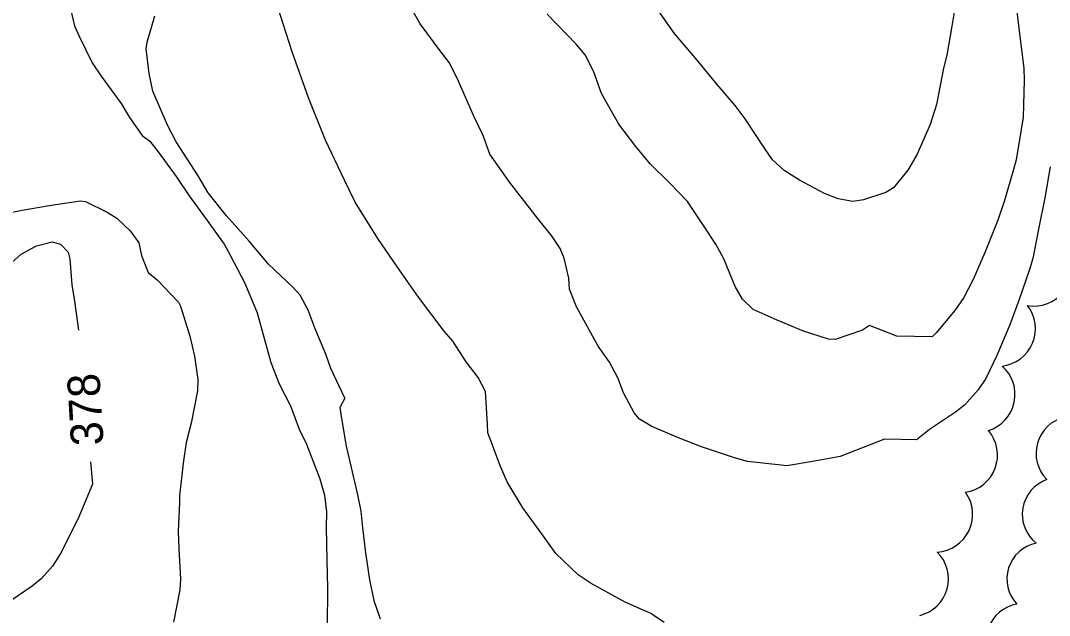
# Model space of a CAD drawing. Extents: x 287698 to 290158, y 5234163 to 5237182.
# Drawn here: x 288457.3 to 288552.3, y 5235862.5 to 5235917.4 of the extents above; entities that cross this region are included whole.
import ezdxf

# ---------------------------------------------------------------- set-up
doc = ezdxf.new("R2010")
doc.units = 0
for name, color, linetype in [('Niveau 1', 7, 'Continuous'), ('Niveau 2', 7, 'Continuous'), ('Niveau 44', 7, 'Continuous')]:
    doc.layers.add(name, color=color, linetype=linetype)

msp = doc.modelspace()

# ---------------------------------------------------------------- linework, layer by layer
at = {"layer": 'Niveau 1'}
for points in [[(288515.63, 5235862.61), (288514.75, 5235862.96), (288513.16, 5235863.68), (288510.03, 5235865.42), (288508.81, 5235866.19), (288506.76, 5235868.18), (288505.77, 5235869.56), (288503.71, 5235872.38), (288502.26, 5235874.79), (288501.66, 5235876.2), (288500.47, 5235879.32), (288500.44, 5235880.12), (288500.26, 5235883.13), (288499.58, 5235884.41), (288498.47, 5235885.86), (288497.23, 5235887.78), (288496.45, 5235888.7), (288494.08, 5235891.82), (288492.12, 5235894.61), (288490.31, 5235897.24), (288488.22, 5235900.59), (288487.25, 5235902.62), (288485.47, 5235906.33), (288483.91, 5235910.24), (288482.41, 5235914.47), (288481.02, 5235918.77)], [(288515.63, 5235862.61), (288516.77, 5235861.83)]]:
    msp.add_lwpolyline(points, dxfattribs=at)
at = {"layer": 'Niveau 2'}
for points in [[(288545.77, 5235939.08), (288547.74, 5235931.7), (288547.66, 5235931.66), (288548.19, 5235928.78), (288548.66, 5235927.21), (288549.54, 5235924.97), (288549.3, 5235922.31), (288549.15, 5235919.63), (288549.23, 5235918.97), (288549.61, 5235915.9), (288549.97, 5235912.96), (288550.01, 5235911.86), (288549.9, 5235908.44), (288549.72, 5235907.32), (288549.26, 5235904.52), (288549.01, 5235903.61), (288548.2, 5235900.76), (288547.56, 5235898.93), (288546.42, 5235896.01), (288545.31, 5235893.46), (288544.42, 5235891.81), (288543.59, 5235890.61), (288541.89, 5235888.53), (288541.5, 5235888.17)], [(288461.61, 5235919.93), (288462.29, 5235916.89), (288462.69, 5235915.99), (288463.93, 5235913.47), (288464.77, 5235912.23), (288466.62, 5235909.71), (288467.37, 5235908.41), (288468.56, 5235906.77), (288469.26, 5235906.23), (288470.02, 5235905.25), (288471.7, 5235902.96), (288472.88, 5235901.2), (288474.56, 5235898.9), (288476.13, 5235896.72), (288476.67, 5235895.7), (288478.02, 5235893.13), (288479.16, 5235890.4), (288479.59, 5235888.81), (288480.45, 5235885.8), (288481.2, 5235883.83), (288482.26, 5235881.79), (288483.05, 5235879.64), (288483.74, 5235878.27), (288484.95, 5235875.06), (288485.39, 5235873.57), (288485.59, 5235872.01), (288485.55, 5235870.56), (288485.61, 5235867.52), (288485.66, 5235864.97), (288485.64, 5235861.46)], [(288543.78, 5235919.66), (288543.32, 5235916.86), (288542.87, 5235914.16), (288542.57, 5235912.97), (288541.91, 5235909.62), (288541.32, 5235907.76), (288540.09, 5235904.97), (288539.27, 5235903.54), (288537.93, 5235901.91), (288537.22, 5235901.49), (288535.17, 5235900.81), (288534.18, 5235900.67), (288532.84, 5235900.91), (288531.56, 5235901.39), (288529.27, 5235902.63), (288527.84, 5235903.52), (288526.78, 5235904.51), (288526.04, 5235905.6), (288524.25, 5235908.29), (288523.33, 5235909.52), (288521.67, 5235911.47), (288519.8, 5235913.71), (288517.71, 5235916.18), (288517.04, 5235917.13), (288515.14, 5235919.88)], [(288540.09, 5235878.68), (288537.12, 5235878.73), (288533.01, 5235877.14), (288530.65, 5235876.7), (288528.08, 5235876.28), (288527.58, 5235876.33), (288524.45, 5235876.67), (288523.25, 5235877), (288520.21, 5235878.03), (288518.07, 5235878.84), (288515.63, 5235879.9), (288514.47, 5235880.57), (288513.98, 5235881.15), (288513.01, 5235882.99), (288512.47, 5235884.39), (288511.72, 5235885.84), (288510.66, 5235887.31), (288508.67, 5235890.94), (288508.03, 5235892.58), (288507.97, 5235893.6), (288507.54, 5235895.44), (288507.17, 5235896.33), (288506.37, 5235897.52), (288505.07, 5235899.11), (288502.52, 5235902.42), (288500.67, 5235905.04), (288500.03, 5235906.75), (288499.18, 5235908.53), (288497.65, 5235912.04), (288496.9, 5235913.5), (288496.06, 5235914.58), (288494.23, 5235917.07), (288493.47, 5235918.43)], [(288487.27, 5235882.52), (288485.99, 5235885.26), (288485.53, 5235886.57), (288484.53, 5235888.9), (288483.89, 5235890.64), (288483.14, 5235892.01), (288482.51, 5235892.74), (288480.22, 5235894.89), (288478.45, 5235897), (288476.33, 5235899.33), (288474.65, 5235901.47), (288473.74, 5235903.02), (288471.7, 5235906.16), (288470.89, 5235907.71), (288469.55, 5235910.85), (288469.19, 5235912.47), (288468.91, 5235914.76), (288469.03, 5235915.38), (288469.71, 5235917.81)], [(288541.5, 5235888.17), (288538.26, 5235888.23), (288535.71, 5235889.21), (288535.08, 5235888.78), (288532.56, 5235887.93), (288531.93, 5235887.96), (288529.64, 5235888.71), (288527.19, 5235889.7), (288524.98, 5235890.71), (288524, 5235891.65), (288523.32, 5235892.83), (288522.27, 5235895.37), (288521.52, 5235896.74), (288520.33, 5235898.53), (288518.93, 5235900.65), (288517.28, 5235902.35), (288515.48, 5235904.14), (288514.13, 5235905.75), (288512.56, 5235907.8), (288510.97, 5235910.63), (288510.22, 5235912.69), (288509.48, 5235914.19), (288508.64, 5235915.2), (288505.96, 5235917.96)], [(288552.4, 5235903.87), (288551.9, 5235900.99), (288551.34, 5235898.12), (288550.8, 5235895.39), (288550.5, 5235894.39), (288549.56, 5235891.63), (288548.67, 5235889.29), (288547.49, 5235886.46), (288546.46, 5235884.33), (288545.77, 5235883.29), (288544.51, 5235881.88), (288543.68, 5235881.23), (288541.26, 5235879.61), (288540.19, 5235878.76), (288540.09, 5235878.68)], [(288456.24, 5235899.61), (288457.46, 5235899.85), (288459.98, 5235900.28), (288462.87, 5235900.71), (288463.31, 5235900.66), (288465.33, 5235899.68), (288466.2, 5235899.12), (288467.46, 5235897.97), (288468.25, 5235896.84), (288468.5, 5235895.69), (288469.1, 5235894.1), (288469.95, 5235893.42), (288471.9, 5235891.38), (288472.1, 5235891.01), (288472.95, 5235888.23), (288473.38, 5235886.39), (288473.69, 5235884.24), (288473.67, 5235883.19), (288473.09, 5235880.19), (288472.62, 5235878.41), (288472.34, 5235876.5), (288471.99, 5235873.51), (288472.01, 5235872.86), (288471.89, 5235870.21), (288471.94, 5235868.63), (288472.08, 5235865.82), (288472.02, 5235864.82), (288471.44, 5235861.84)], [(288456.51, 5235895.02), (288457.38, 5235895.81), (288458.81, 5235896.57), (288460.25, 5235896.95), (288461.02, 5235896.72), (288461.71, 5235896), (288461.88, 5235895.38), (288462.07, 5235892.96), (288462.32, 5235891.46), (288462.66, 5235888.8)], [(288487.27, 5235882.52), (288486.8, 5235881.65), (288486.95, 5235880.62), (288487.39, 5235878.09), (288487.84, 5235876.1), (288488.45, 5235873.59), (288488.74, 5235872.08), (288488.89, 5235870.55), (288489.17, 5235868.23), (288489.56, 5235865.73), (288489.96, 5235863.85), (288490.52, 5235862.14)], [(288463.78, 5235876.63), (288463.97, 5235874.57)], [(288463.97, 5235874.57), (288462.64, 5235871.4), (288461, 5235868.17), (288460.26, 5235866.99), (288459.24, 5235865.84), (288458.39, 5235865.16), (288456.16, 5235863.62)]]:
    msp.add_lwpolyline(points, dxfattribs=at)
at = {"layer": 'Niveau 44'}
msp.add_arc((288541.761, 5235871.792), 3.489, 273.59976, 35.53815, dxfattribs=at)
for centre, major_axis, ratio, start_param, end_param in [((288550.893, 5235894.517), (2.486, -2.471), 0.999697, 5.330275, 7.458758), ((288547.576, 5235888.932), (3.176, -1.43), 0.996194, 5.244484, 7.367338), ((288545.679, 5235882.847), (3.41, -0.719), 0.999224, 5.220244, 7.348221), ((288554.524, 5235877.427), (-3.294, 0.933), 0.999978, 5.219441, 7.3473), ((288544.066, 5235877.259), (3.144, -1.495), 0.999508, 5.310183, 7.434684), ((288553.26, 5235871.783), (-3.362, 0.658), 0.99636, 5.247451, 7.371644), ((288551.835, 5235865.797), (-3.263, 1.048), 0.988806, 5.230175, 7.341035), ((288539.54, 5235865.837), (3.255, -1.22), 0.999507, 5.309171, 7.434279), ((288549.98, 5235860.145), (-3.261, 1.16), 0.983034, 5.23801, 7.333897)]:
    msp.add_ellipse(centre, major_axis=major_axis, ratio=ratio, start_param=start_param, end_param=end_param, dxfattribs=at)

# ---------------------------------------------------------------- texts
at = {"layer": 'Niveau 2'}
msp.add_text('378', height=2.9999, rotation=93.4493, dxfattribs=at).set_placement((288465, 5235878.21))

doc.saveas('drawing.dxf')
